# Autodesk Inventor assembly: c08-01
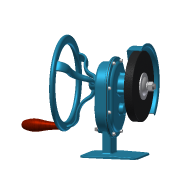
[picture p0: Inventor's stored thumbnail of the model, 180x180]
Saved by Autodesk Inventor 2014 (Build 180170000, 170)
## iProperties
Created: 2010-12
Part Number: c08-01
Document SubType Name: Assembly
Designer: Thom Tremblay
Author: Thom Tremblay
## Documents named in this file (28)
- C:\Inventor 2014 Essentials\Assemblies\Chapter 08\c08-01.iam
- C:\Inventor 2014 Essentials\Parts\Chapter 08\c08-01.ipt
- C:\Inventor 2014 Essentials\Parts\Chapter 08\c08-02.ipt
- C:\Inventor 2014 Essentials\Assemblies\Chapter 08\c08-01\Design Accelerator\Spur Gears1.iam
- C:\Inventor 2014 Essentials\Assemblies\Chapter 08\c08-01\Design Accelerator\Spur Gears2.iam
- C:\Inventor 2014 Essentials\Parts\Chapter 08\c08-03.ipt
- C:\Inventor 2014 Essentials\Parts\Chapter 08\c08-04.ipt
- C:\Inventor 2014 Essentials\Parts\Chapter 08\c08-05.ipt
- C:\Inventor 2014 Essentials\Parts\Chapter 08\c08-08.ipt
- C:\Inventor 2014 Essentials\Parts\Chapter 08\c08-06.ipt
- C:\Inventor 2014 Essentials\Parts\Chapter 08\c08-07.ipt
- C:\Inventor 2014 Essentials\Content Center Files\en-US\ANSI B93.98M\ANSI_B93.98M - 15x35x7-Type 2.ipt
- C:\Inventor 2014 Essentials\Content Center Files\en-US\SKF B - angular contact\SKF B7202 BE.ipt
- C:\Inventor 2014 Essentials\Content Center Files\en-US\IS 7483\IS 7483 - M4 x 8.ipt
- C:\Inventor 2014 Essentials\Assemblies\Chapter 08\c08-01\Design Accelerator\Bolted Connection3.iam
- C:\Inventor 2014 Essentials\Content Center Files\en-US\ISO 2795  F\ISO 2795 - 10 x 14 x 10F.ipt
- C:\Inventor 2014 Essentials\Assemblies\Chapter 08\c08-01\Design Accelerator\Shaft4.iam
- C:\Inventor 2014 Essentials\Assemblies\Chapter 08\c08-01\Design Accelerator\Shaft6.iam
- C:\Inventor 2014 Essentials\Assemblies\Chapter 08\c08-01\Design Accelerator\Spur Gears4.iam
- C:\Inventor 2014 Essentials\Assemblies\Chapter 08\c08-01\Design Accelerator\Shaft5.iam
- C:\Inventor 2014 Essentials\Content Center Files\en-US\STN 022930\STN 022930 - 10.ipt
- C:\Inventor 2014 Essentials\Content Center Files\en-US\STN 022930\STN 022930 - 15.ipt
- C:\Inventor 2014 Essentials\Assemblies\Chapter 08\c08-01\Design Accelerator\Spur Gears5.iam
- C:\Inventor 2014 Essentials\Content Center Files\en-US\DIN 128\DIN 128 - A12.ipt
- C:\Inventor 2014 Essentials\Assemblies\Chapter 08\c08-01\Design Accelerator\Bolted Connection4.iam
- C:\Inventor 2014 Essentials\Content Center Files\en-US\ISO 4032\ISO 4032 - M12ISO.ipt
- C:\Inventor 2014 Essentials\Content Center Files\en-US\ISO 4145 T8\ISO 4145 Plug T8 1_8.ipt
- C:\Inventor 2014 Essentials\Assemblies\Chapter 08\c08-01\Design Accelerator\Key Connection1.iam
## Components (32 placed, 21 different names)
1. c08-01:1 — Insert:1, Angle:1, Flush:3, Insert:27, Insert:28, Insert:39
2. c08-02:1 — Insert:1, Angle:1, Insert:17, Insert:18, Insert:25, Insert:26, Mate:3, Insert:40, Mate:10, Mate:11
3. ANSI/B93.98M 15x35x7-Type 2:1 — Insert:40
4. Spur Gears:1 [sub-assembly]
5. Spur Gears:2 [sub-assembly] — Rotation:3, Rotation:2, Mate:4, Flush:4, Angle:15
6. c08-03:1 — Flush:3
7. c08-04:1 — Insert:10, Insert:35, Angle:9, Mate:5, Angle:13
8. c08-05:1 — Insert:10
9. c08-08:1 — Insert:13, Insert:16, Insert:36
10. c08-08:2 — Insert:13
11. c08-06:1 — Insert:16, Angle:11, Angle:12
12. c08-07:1 — Insert:17, Insert:18
13. SKF B- Angular contact SKF B7202 BE:1 — Insert:25
14. IS 7483 M4 x 8:1
15. IS 7483 M4 x 8:2
16. Bolted Connection:2 [sub-assembly] — Mate:10, Mate:11
17. ISO 2795 (Flanged) 10 x 14 x 10:1 — Insert:26
18. ISO 2795 (Flanged) 10 x 14 x 10:2 — Insert:27, Insert:30
19. ISO 2795 (Flanged) 10 x 14 x 10:3 — Insert:28, Insert:34
20. Shaft:1 [sub-assembly] — Rotation:1, Insert:34, Insert:35, Angle:9, Mate:6
21. Shaft:2 [sub-assembly] — Insert:30, Rotation:1, Flush:3, Rotation:3, Mate:4, Flush:4, Flush:5, Angle:14, Mate:9, Angle:15
22. Spur Gears:3 [sub-assembly]
23. Shaft:3 [sub-assembly] — Flush:3, Mate:3, Rotation:2, Insert:36, Angle:12
24. STN 022930 10:1
25. STN 022930 15:1
26. STN 022930 15:2
27. Spur Gears:4 [sub-assembly]
28. DIN 128 A12:1 — Angle:10
29. Bolted Connection:3 [sub-assembly] — Mate:5, Mate:6
30. ISO 4032 M12:1 — Angle:10, Angle:11
31. ISO 4145 Plug T8 1/8:1 — Insert:39
32. Key Connection:1 [sub-assembly] — Flush:5, Angle:14, Mate:9
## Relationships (38: Insert 16, Angle 8, Mate 7, Flush 4, RelateRotation 3)
- Insert:1: c08-01:1 ↔ c08-02:1
- Angle:1: c08-01:1 ↔ c08-02:1
- Flush:3: c08-01:1 ↔ c08-03:1
- Insert:10: c08-04:1 ↔ c08-05:1
- Insert:13: c08-08:1 ↔ c08-08:2
- Insert:16: c08-08:1 ↔ c08-06:1
- Insert:17: c08-02:1 ↔ c08-07:1
- Insert:18: c08-02:1 ↔ c08-07:1
- Insert:25: c08-02:1 ↔ SKF B- Angular contact SKF B7202 BE:1
- Insert:26: c08-02:1 ↔ ISO 2795 (Flanged) 10 x 14 x 10:1
- Insert:27: c08-01:1 ↔ ISO 2795 (Flanged) 10 x 14 x 10:2
- Insert:28: c08-01:1 ↔ ISO 2795 (Flanged) 10 x 14 x 10:3
- Insert:30: ISO 2795 (Flanged) 10 x 14 x 10:2 ↔ Shaft:2
- Rotation:1 [RelateRotation]: Shaft:1 ↔ Shaft:2
- Flush:3: Shaft:2 ↔ Shaft:3
- Mate:3: c08-02:1 ↔ Shaft:3
- Insert:34: ISO 2795 (Flanged) 10 x 14 x 10:3 ↔ Shaft:1
- Insert:35: c08-04:1 ↔ Shaft:1
- Angle:9: c08-04:1 ↔ Shaft:1
- Rotation:2 [RelateRotation]: Spur Gears:2 ↔ Shaft:3
- Rotation:3 [RelateRotation]: Spur Gears:2 ↔ Shaft:2
- Mate:4: Spur Gears:2 ↔ Shaft:2
- Flush:4: Spur Gears:2 ↔ Shaft:2
- Insert:36: c08-08:1 ↔ Shaft:3
- Mate:5: c08-04:1 ↔ Bolted Connection:3
- Mate:6: Shaft:1 ↔ Bolted Connection:3
- Angle:10: DIN 128 A12:1 ↔ ISO 4032 M12:1
- Angle:11: c08-06:1 ↔ ISO 4032 M12:1
- Angle:12: c08-06:1 ↔ Shaft:3
- Insert:39: c08-01:1 ↔ ISO 4145 Plug T8 1/8:1
- Angle:13: c08-04:1
- Flush:5: Shaft:2 ↔ Key Connection:1
- Angle:14: Shaft:2 ↔ Key Connection:1
- Mate:9: Shaft:2 ↔ Key Connection:1
- Angle:15: Spur Gears:2 ↔ Shaft:2
- Insert:40: c08-02:1 ↔ ANSI/B93.98M 15x35x7-Type 2:1
- Mate:10: c08-02:1 ↔ Bolted Connection:2
- Mate:11: c08-02:1 ↔ Bolted Connection:2
